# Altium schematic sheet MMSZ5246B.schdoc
size 127 x 101 mm
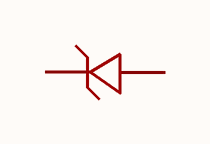
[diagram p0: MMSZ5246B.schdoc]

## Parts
ZD?  mmsz5246b_c21544  [SOD-123_L2.8-W1.8-LS3.7-RD]  (value not drawn)

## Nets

Not connected (* = marked no-connect by the designer): ZD? 1(K) 2(A)

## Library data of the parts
ZD? = mmsz5246b_c21544: 二极管配置:1个独立式;稳压值(标称值):16V;稳压值(范围值):15.2V~16.8V;耗散功率(Pd):350mW;; Manufacturer: CJ(江苏长电/长晶); AddInBom: yes; ModelId: 7884390a25fb4c08947731ebfba7e3f8; ModelTransform: 144.8816,62.992,0,0,0,0,0,0,0; Diode Configuration: 1个独立式; Zener Voltage(Nom): 16V; Reverse Leakage Current (Ir): 100nA@12V; Pd - Power Dissipation: 350mW; Impedance(Zzt): 17Ω; Impedance(Zzk): 600Ω; Operating Junction Temperature Range: -65℃~+150℃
